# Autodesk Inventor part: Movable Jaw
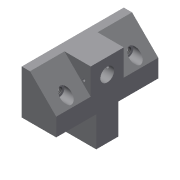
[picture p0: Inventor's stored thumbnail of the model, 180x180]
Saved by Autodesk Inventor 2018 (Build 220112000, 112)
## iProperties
Shininess: 77.0
Length Units: 11269
Angle Units: 11279
Time Units: 11290
Mass Units: 11283
Length Display Precision: 3
Angle Display Precision: 2
Created: 2002-02
Part Number: Movable Jaw
Document SubType Name: Modeling
Designer: ***
Density: 1 g/cm^3
Material: Generic
Mass: 56.5588 g
Surface Area: 124.299 cm^2
Volume: 56.5588 cm^3
Appearance: Default
Density: 0.0
Volumn: 0.0
Area: 0.0
PropertySet Name: Model Information
Control State: 0
Master: False
Checked Out: False
Author: ***
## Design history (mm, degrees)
sketch "Sketch2"
  geometry: L1 (2.39, 41.509)-(2.39, 9.509); L2 (2.39, 9.509)-(-22.61, 9.509); L3 (-22.61, 9.509)-(-22.61, 22.509); L4 (-22.61, 22.509)-(-3.61, 41.509); L5 (-3.61, 41.509)-(2.39, 41.509)
  constraints: 10 end point, 2 parallel, 1 perpendicular, 1 vertical
  dimensions: "d0" = 25 distance of L1.end L2.end; "d2" = 13 distance of L2.end L3.end; "d3" = 32 distance between parallel lines of L5 L2; "d4" = 6 distance of L4.end L1.start
extrude "Extrusion1" new body sketch "Sketch2" stored distance "d5" = 74; taper "d6" = 0 deg
sketch "Sketch3"
  geometry: L1 (-19, 25)-(11, 25); L2 (11, 25)-(11, 49); L3 (11, 49)-(-19, 49); L4 (-19, 49)-(-19, 25); L5 (0, 0)-(13, 0) reference; L6 (-19, 74)-(-19, 0) reference; L7 (11.924, 29)-(35, 29); L8 (35, 29)-(35, 45); L9 (35, 45)-(11.924, 45); L10 (11.924, 45)-(11.924, 29); L11 (13, 74)-(13, 0) reference
  constraints: 16 end point, 4 parallel, 2 horizontal, 2 perpendicular, 1 collinear
  dimensions: "d7" = 24 distance of L3.end L1.start; "d8" = 30 distance of L1.start L1.end; "d9" = 25 distance between parallel lines of L5 L1; "d10" = 16 distance of L7.end L8.end; "d11" = 4 distance between parallel lines of L3 L9; "d12" = 22 distance between parallel lines of L11 L8
extrude "Extrusion2" join sketch "Sketch3" distance "d13" = 25; taper "d14" = 0 deg
sketch "Sketch4"
  geometry: L1 (-19, -25)-(-19, -49) reference; L2 (-19, -49)-(0, -49) reference; 1 further point
  dimensions: "d15" = 11 distance from line of L1 point (-8, -37); "d16" = 12 distance from line of L2 point (-8, -37)
hole "Hole1" sketch "Sketch4" at (-8, -37) diameter "d17" = 10; stored, may be unused: countersink angle "d21" = 82 deg, drill point angle "d23" = 0 deg; dims "d18" = 6, "d19" = 4, "d20" = 2, "d22" = 13
sketch "Sketch5"
  geometry: L1 (-19, -49)-(-19, -74) reference; L2 (0, -74)-(13, -74) reference; 1 further point
  dimensions: "d24" = 14 distance from line of L1 point (-5, -62); "d25" = 12 distance from line of L2 point (-5, -62)
hole "Hole2" sketch "Sketch5" at (-5, -62) diameter "d26" = 4.917; stored, may be unused: countersink angle "d30" = 82 deg, drill point angle "d32" = 0 deg; dims "d27" = 12, "d28" = 8, "d29" = 10, "d31" = 17.1
mirror "Mirror1"
sketch "Sketch6"
  geometry: L1 (0, 19)-(0, 0) reference; 1 further point
  dimensions: "d33" = 5 distance from line of L1 point (-5, 8); "d34" = 11 vertical distance of L1.start point (-5, 8)
hole "Hole3" sketch "Sketch6" at (-5, 8) diameter "d35" = 2; stored, may be unused: countersink angle "d39" = 82 deg, drill point angle "d41" = 0 deg; dims "d36" = 6, "d37" = 8, "d38" = 10, "d40" = 13
body "Solid1"
